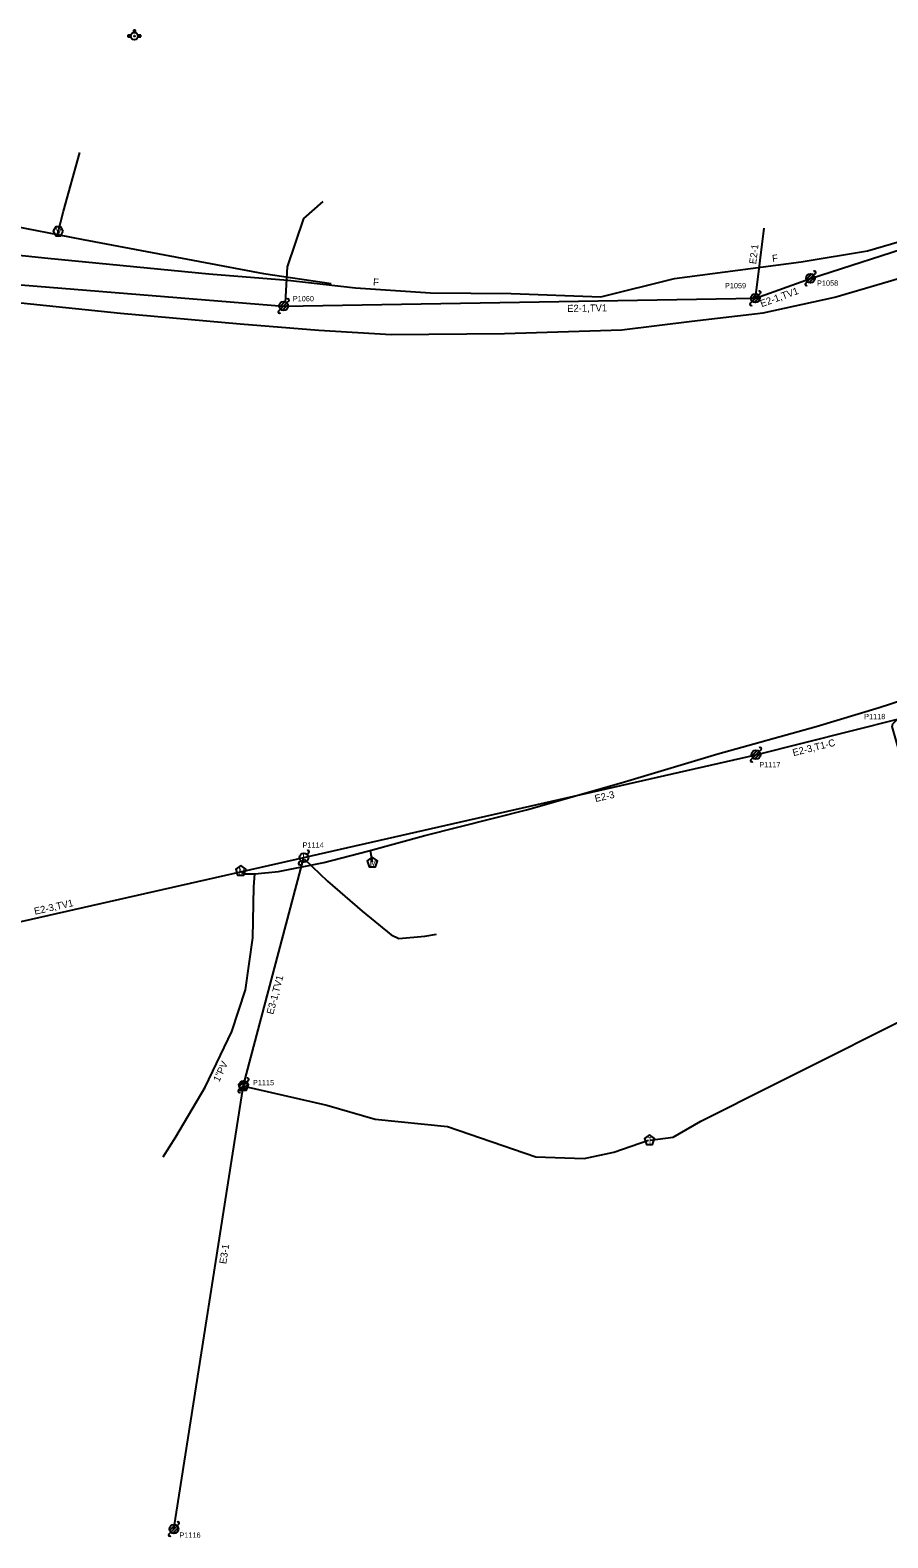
# Model space of a CAD drawing. Extents: x 1741604 to 1825760, y 1164229 to 1194908.
# Drawn here: x 1803491 to 1803976, y 1187568 to 1188422 of the extents above; entities that cross this region are included whole.
import ezdxf

# ---------------------------------------------------------------- set-up
doc = ezdxf.new("R2010")
doc.units = 0
for name, color, linetype in [('RD_EX_SU_Elec', 7, 'Continuous'), ('RD_EX_SU_H2O', 7, 'Continuous'), ('RD_EX_SU_Ovhd', 7, 'Continuous'), ('RD_EX_SU_Pole', 7, 'Continuous'), ('RD_EX_SU_Telecom', 7, 'Continuous'), ('RD_EX_SU_TX_H2O', 7, 'Continuous'), ('RD_EX_SU_TX_Pole', 7, 'Continuous'), ('RD_EX_SU_TX_Telecom', 7, 'Continuous')]:
    doc.layers.add(name, color=color, linetype=linetype)

# ---------------------------------------------------------------- blocks, each defined once
blk = doc.blocks.new('SUE_WV')
at = {"layer": 'RD_EX_SU_H2O'}
blk.add_lwpolyline([(2.89, 0), (1.44, 2.5), (-1.44, 2.5), (-2.89, 0), (-1.44, -2.5), (1.44, -2.5)], close=True, dxfattribs=at)
blk.add_text('V', height=3.75, dxfattribs=at).set_placement((-1.43, -1.88))
blk = doc.blocks.new('SUE_WFH')
at = {"layer": 'RD_EX_SU_H2O'}
for p, q in [((-2.01, 0.6), (-3.65, 0.6)), ((-3.65, 0.6), (-3.65, -0.45)), ((-0.48, 3.38), (-0.48, 2.04)), ((0.57, 3.38), (-0.48, 3.38)), ((0.57, 2.02), (0.57, 3.38)), ((3.7, 0.6), (2.01, 0.6)), ((3.7, -0.45), (3.7, 0.6)), ((-3.65, -0.45), (-2.05, -0.45)), ((2.05, -0.45), (3.7, -0.45))]:
    blk.add_line(p, q, dxfattribs=at)
for radius in [2.1, 0.263]:
    blk.add_circle((0, 0), radius, dxfattribs=at)
for start, end in [(163.3387, 192.31502), (74.24552, 103.21276), (347.68498, 16.6613)]:
    blk.add_arc((0, 0), 2.1, start, end, dxfattribs=at)
blk = doc.blocks.new('SUE_WM')
at = {"layer": 'RD_EX_SU_H2O'}
blk.add_lwpolyline([(0, 3.05), (-2.9, 0.94), (-1.79, -2.47), (1.79, -2.47), (2.9, 0.94)], close=True, dxfattribs=at)
blk.add_text('M', height=3.75, dxfattribs=at).set_placement((-1.43, -1.88))
blk = doc.blocks.new('SUE_TPP')
at = {"layer": 'RD_EX_SU_Telecom'}
blk.add_lwpolyline([(0, 3), (-2.85, 0.93), (-1.76, -2.43), (1.76, -2.43), (2.85, 0.93)], close=True, dxfattribs=at)
blk.add_text('T', height=3.75, dxfattribs=at).set_placement((-1.25, -1.88))
blk = doc.blocks.new('SUE_PP')
at = {"layer": 'RD_EX_SU_Pole'}
for p, q in [((-2.41, -0.65), (0.65, 2.41)), ((-1.77, -1.77), (1.77, 1.77)), ((-0.65, -2.41), (2.41, 0.65)), ((1.77, 1.77), (2.83, 2.83)), ((-2.83, -2.83), (-1.77, -1.77))]:
    blk.add_line(p, q, dxfattribs=at)
blk.add_circle((0, 0), 2.5, dxfattribs=at)
for centre, start, end in [((2.3, 3.36), 315, 135), ((-2.3, -3.36), 135, 315)]:
    blk.add_arc(centre, 0.75, start, end, dxfattribs=at)

msp = doc.modelspace()

# ---------------------------------------------------------------- linework, layer by layer
at = {"layer": 'RD_EX_SU_Elec'}
msp.add_lwpolyline([(1803646.22, 1187952.91), (1803659.14, 1187940.36), (1803678.78, 1187923.36), (1803695.25, 1187910), (1803699.62, 1187907.88), (1803714.27, 1187909.27), (1803720.88, 1187910.42)], dxfattribs=at)
at = {"layer": 'RD_EX_SU_H2O'}
msp.add_line((1803683.29, 1187957.72), (1803684.39, 1187951.35), dxfattribs=at)
for points in [[(1803506.31, 1188306.51), (1803509.69, 1188319.77), (1803518.96, 1188352.92)], [(1803346.17, 1188342.4), (1803388.46, 1188339.23), (1803431.18, 1188325.25), (1803474.23, 1188312.82), (1803520.85, 1188303.65), (1803579.96, 1188292.59), (1803622.9, 1188284.49), (1803661.16, 1188278.85)], [(1803566.11, 1187784.25), (1803573.38, 1187795.66), (1803589.92, 1187823.65), (1803604.93, 1187855.25), (1803612.83, 1187878.88), (1803616.89, 1187908.31), (1803617.47, 1187937.1), (1803618.11, 1187944.48), (1803631.52, 1187945.83), (1803657.13, 1187950.99), (1803682.49, 1187957.5), (1803714.26, 1187966.17), (1803771.75, 1187980.84), (1803825.31, 1187996.14), (1803880.12, 1188012.45), (1803935.86, 1188027.98), (1803971.49, 1188038.71), (1803991.8, 1188045.38), (1804051.15, 1188069.06), (1804069.79, 1188075.91), (1804087.18, 1188064.75)], [(1803610.74, 1187945.43), (1803612.77, 1187944.56), (1803618.11, 1187944.48)]]:
    msp.add_lwpolyline(points, dxfattribs=at)
at = {"layer": 'RD_EX_SU_Ovhd'}
for p, q in [((1803932.53, 1188281.73), (1804064.58, 1188324.24)), ((1803901.36, 1188270.46), (1803906.35, 1188310.06)), ((1803352.26, 1188288.73), (1803634.34, 1188266.05)), ((1803901.36, 1188270.46), (1803932.53, 1188281.73)), ((1803634.34, 1188266.05), (1803901.36, 1188270.46)), ((1803901.7, 1188011.98), (1803982.65, 1188032.23)), ((1803645.82, 1187953.68), (1803901.7, 1188011.98)), ((1803431.1, 1187905.14), (1803645.82, 1187953.68)), ((1803611.66, 1187824.8), (1803645.82, 1187953.68)), ((1803572.24, 1187573.5), (1803611.66, 1187824.8))]:
    msp.add_line(p, q, dxfattribs=at)
at = {"layer": 'RD_EX_SU_Pole'}
for p, q in [((1803930.11, 1188281.08), (1803933.17, 1188284.14)), ((1803930.76, 1188279.96), (1803934.29, 1188283.5)), ((1803931.88, 1188279.31), (1803934.94, 1188282.38)), ((1803934.29, 1188283.5), (1803935.35, 1188284.56)), ((1803903.13, 1188272.23), (1803904.19, 1188273.29)), ((1803929.7, 1188278.9), (1803930.76, 1188279.96)), ((1803631.92, 1188265.4), (1803634.98, 1188268.46)), ((1803632.57, 1188264.28), (1803636.1, 1188267.81)), ((1803633.69, 1188263.63), (1803636.75, 1188266.69)), ((1803636.1, 1188267.81), (1803637.17, 1188268.87)), ((1803898.54, 1188267.63), (1803899.6, 1188268.69)), ((1803898.95, 1188269.81), (1803902.01, 1188272.87)), ((1803899.6, 1188268.69), (1803903.13, 1188272.23)), ((1803900.72, 1188268.04), (1803903.78, 1188271.1)), ((1803631.51, 1188263.22), (1803632.57, 1188264.28)), ((1803898.87, 1188009.15), (1803899.93, 1188010.21)), ((1803899.29, 1188011.33), (1803902.35, 1188014.39)), ((1803899.93, 1188010.21), (1803903.47, 1188013.75)), ((1803901.05, 1188009.56), (1803904.11, 1188012.63)), ((1803903.47, 1188013.75), (1803904.53, 1188014.81)), ((1803642.99, 1187950.85), (1803644.05, 1187951.91)), ((1803647.58, 1187955.45), (1803648.64, 1187956.51)), ((1803608.83, 1187821.97), (1803609.89, 1187823.03)), ((1803609.25, 1187824.16), (1803612.31, 1187827.22)), ((1803609.89, 1187823.03), (1803613.43, 1187826.57)), ((1803611.02, 1187822.39), (1803614.08, 1187825.45)), ((1803613.43, 1187826.57), (1803614.49, 1187827.63))]:
    msp.add_line(p, q, dxfattribs=at)
for centre in [(1803932.53, 1188281.73), (1803634.34, 1188266.05), (1803901.36, 1188270.46), (1803901.7, 1188011.98), (1803645.82, 1187953.68), (1803611.66, 1187824.8)]:
    msp.add_circle(centre, 2.5, dxfattribs=at)
for centre, start, end in [((1803934.82, 1188285.09), 315, 135), ((1803903.66, 1188273.82), 315, 135), ((1803930.23, 1188278.37), 135, 315), ((1803636.63, 1188269.4), 315, 135), ((1803899.07, 1188267.1), 135, 315), ((1803632.04, 1188262.69), 135, 315), ((1803899.4, 1188008.62), 135, 315), ((1803904, 1188015.34), 315, 135), ((1803648.11, 1187957.04), 315, 135), ((1803643.52, 1187950.32), 135, 315), ((1803609.36, 1187821.44), 135, 315), ((1803613.96, 1187828.16), 315, 135)]:
    msp.add_arc(centre, 0.75, start, end, dxfattribs=at)
at = {"layer": 'RD_EX_SU_Telecom'}
for points in [[(1803344.36, 1188363.82), (1803343.6, 1188331.82), (1803346.83, 1188319.2), (1803351.52, 1188314.2), (1803361.46, 1188310.72), (1803391.28, 1188305), (1803430.33, 1188300.6), (1803500.91, 1188293.24), (1803591.93, 1188284.37), (1803636.7, 1188280.61), (1803675.06, 1188276.4), (1803717.47, 1188273.48), (1803763.22, 1188273.06), (1803813.9, 1188271.23), (1803855.58, 1188281.71), (1803927.29, 1188291.05), (1803964.81, 1188297.36), (1804010.06, 1188310.56)], [(1803325.47, 1188356.28), (1803325.26, 1188321.89), (1803326.73, 1188311.93), (1803329.24, 1188304.36), (1803337.23, 1188295.4), (1803353.85, 1188286.22), (1803378.04, 1188280.86), (1803404.82, 1188277.25), (1803438.92, 1188272.87), (1803480.15, 1188268.47), (1803542.03, 1188261.99), (1803609.7, 1188255.94), (1803654.25, 1188252.4), (1803695.25, 1188249.91), (1803759.39, 1188250.52), (1803825.78, 1188252.61), (1803865.47, 1188257.51), (1803905.82, 1188262.21), (1803946.35, 1188271.02), (1804006.79, 1188288.77)], [(1803635.3, 1188268.11), (1803636.57, 1188288.31), (1803645.85, 1188315.64), (1803656.73, 1188325.34)], [(1803841.73, 1187793.66), (1803854.83, 1187795.44), (1803870.54, 1187804.49), (1803911.41, 1187825.12), (1804002.66, 1187870.77), (1804012.77, 1187878.25), (1804016.71, 1187886.35), (1804016.08, 1187897.64), (1804006.57, 1187931.58), (1803986.36, 1188001.56), (1803978.74, 1188028.01), (1803979.09, 1188029.38), (1803981.8, 1188032.01)], [(1803611.82, 1187824.34), (1803658.8, 1187813.55), (1803686.1, 1187805.54), (1803727.12, 1187801.41), (1803777.02, 1187784.29), (1803804.44, 1187783.34), (1803821.18, 1187786.97), (1803840.94, 1187793.62)]]:
    msp.add_lwpolyline(points, dxfattribs=at)

# ---------------------------------------------------------------- block references
at = {"layer": 'RD_EX_SU_H2O'}
for name, p in [('SUE_WFH', (1803549.84, 1188418.9)), ('SUE_WV', (1803506.74, 1188308.4)), ('SUE_WM', (1803610.1, 1187946.17)), ('SUE_WM', (1803684.49, 1187950.92))]:
    msp.add_blockref(name, p, dxfattribs=at)
at = {"layer": 'RD_EX_SU_Pole'}
msp.add_blockref('SUE_PP', (1803572.24, 1187573.5), dxfattribs=at)
at = {"layer": 'RD_EX_SU_Telecom'}
for p in [(1803611.56, 1187824.35), (1803841.41, 1187793.63)]:
    msp.add_blockref('SUE_TPP', p, dxfattribs=at)

# ---------------------------------------------------------------- texts
at = {"layer": 'RD_EX_SU_Ovhd'}
for s, rotation, p in [('E2-1', 82.82359, (1803901.76, 1188289.62)), ('E2-1,TV1', 19.8851, (1803904.93, 1188265.37)), ('E2-1,TV1', 0.94649, (1803794.87, 1188262.7)), ('E2-3,T1-C', 14.04494, (1803922.97, 1188011.12)), ('E2-3', 12.83442, (1803810.9, 1187985.14)), ('E2-3,TV1', 12.73877, (1803493.58, 1187921.32)), ('E3-1,TV1', 75.15756, (1803628.42, 1187864.61)), ('E3-1', 81.0851, (1803601.82, 1187723.35))]:
    msp.add_text(s, height=4, rotation=rotation, dxfattribs=at).set_placement(p)
at = {"layer": 'RD_EX_SU_Pole'}
msp.add_text('L', height=4, dxfattribs=at).set_placement((1803644.95, 1187951.68))
at = {"layer": 'RD_EX_SU_TX_H2O'}
msp.add_text('1"PV', height=4, rotation=64.59256, dxfattribs=at).set_placement((1803597.83, 1187826.32))
at = {"layer": 'RD_EX_SU_TX_Pole'}
for s, p in [('P1059', (1803884.14, 1188276.11)), ('P1058', (1803936.26, 1188277.54)), ('P1060', (1803639.52, 1188268.74)), ('P1118', (1803962.93, 1188032.1)), ('P1117', (1803903.59, 1188004.81)), ('P1114', (1803645.05, 1187959.32)), ('P1115', (1803616.97, 1187824.8)), ('P1116', (1803575.37, 1187568.54))]:
    msp.add_text(s, height=3, dxfattribs=at).set_placement(p)
at = {"layer": 'RD_EX_SU_TX_Telecom'}
for rotation, p in [(7.41729, (1803911.09, 1188290.96)), (356.06389, (1803684.83, 1188277.73))]:
    msp.add_text('F', height=4, rotation=rotation, dxfattribs=at).set_placement(p)

doc.saveas('drawing.dxf')
